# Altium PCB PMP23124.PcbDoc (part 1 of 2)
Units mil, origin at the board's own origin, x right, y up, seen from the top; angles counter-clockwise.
Board outline 2625 x 1500 mil, 2 copper layers (Top Layer, Bottom Layer), stack 62 mil thick; 59 components, 31 nets, 143 pads, 28 vias.
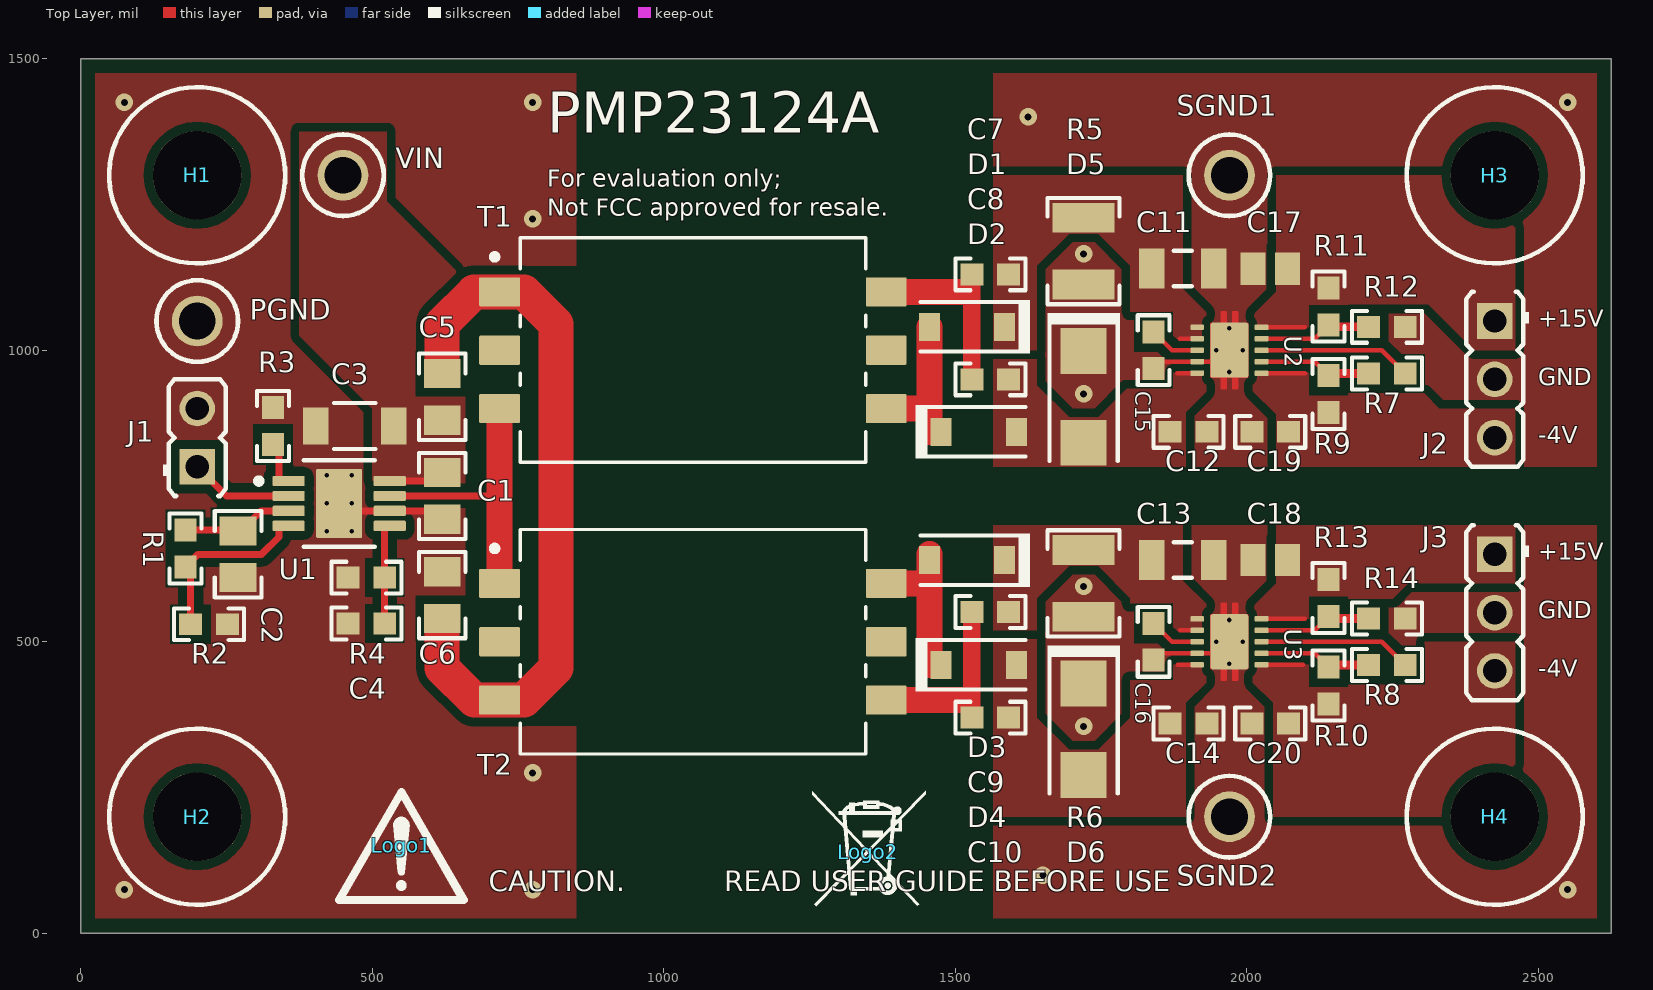
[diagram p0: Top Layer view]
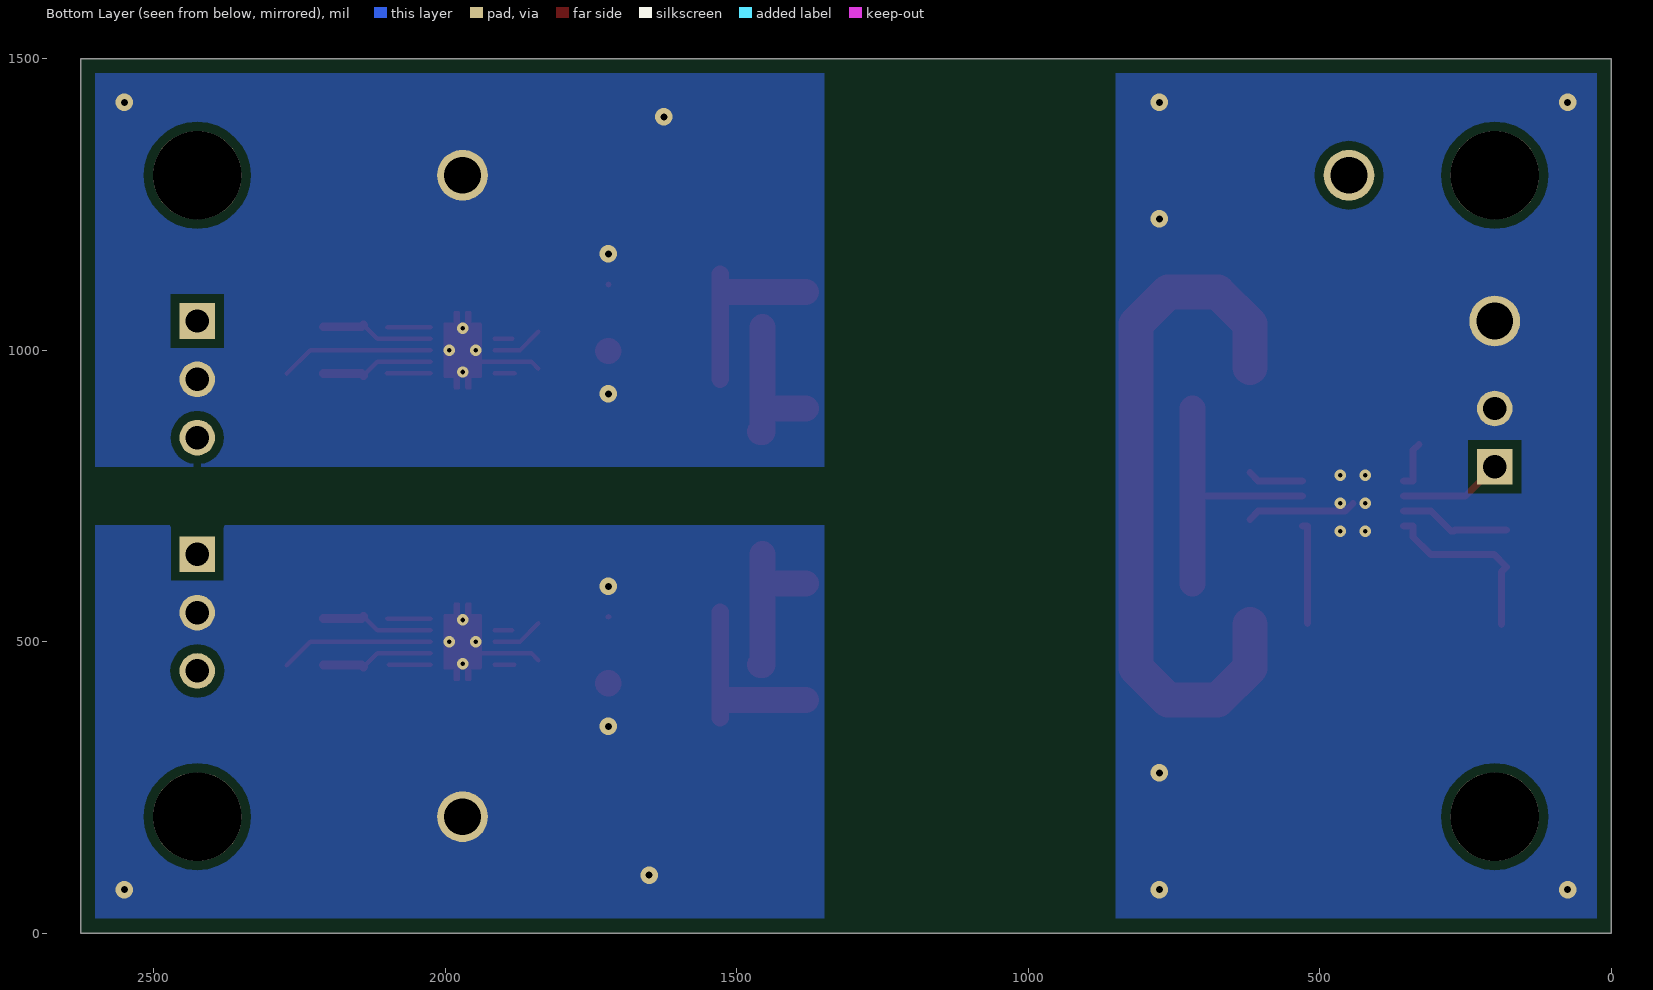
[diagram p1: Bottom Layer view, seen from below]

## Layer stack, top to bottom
Top Solder: solder mask 0.4, Solder Resist, Dk 3.5
Top Layer: signal copper 1.4
Dielectric1: core 59.2, FR-4 High Tg, Dk 4.8
Bottom Layer: signal copper 1.4
Bottom Solder: solder mask 0.4, Solder Resist, Dk 3.5

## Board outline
0,0 2625,0 2625,1500 0,1500

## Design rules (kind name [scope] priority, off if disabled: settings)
AcuteAngle [All] p1: minimum=4.50000000000000E+0001 checktracksonly=FALSE
AssemblyTestPointUsage [All] p1: valid=2
BoardOutlineClearance BoardOutlineClearance_MountingHoles [OnCopper and InComponentClass('Mounting Holes')] p1: gap=25 ignorepadtopadclearanceinfootprint=FALSE
BoardOutlineClearance BoardOutlineClearance_Poly [OnCopper and InPoly] p2: gap=25 ignorepadtopadclearanceinfootprint=FALSE
BoardOutlineClearance [OnCopper and Not InComponentClass('Logo') and not InComponentClass('FiducialMark') and not InRegion(1000,500,4000,800)] p3: gap=25 ignorepadtopadclearanceinfootprint=FALSE
Clearance Clearance_2 [InNetClass('HV') vs Not InNetClass('HV')] p1: gap=60 ignorepadtopadclearanceinfootprint=FALSE
Clearance Clearance_1 [InNetClass('MV') vs Not InNetClass('MV')] p2: gap=30 ignorepadtopadclearanceinfootprint=FALSE
Clearance Clearance_Keepouts [((IsTrack Or IsArc) And Not InPoly) And IsFree and IsKeepOut vs ((IsTrack Or IsArc) And Not InPoly) And IsFree and IsKeepOut] p3: gap=0 ignorepadtopadclearanceinfootprint=FALSE
Clearance Clearance_BoardEdge_MountingHoles [OnCopper and InComponentClass('Mounting Holes') vs IsKeepOut] p4: gap=40 ignorepadtopadclearanceinfootprint=FALSE except(0: Arc-Hole Track-Hole SMDPad-Hole THPad-Hole Via-Hole Fill-Hole Poly-Hole Region-Hole Text-Hole)
Clearance Clearance_BoardEdge_Poly [OnCopper and InPoly vs IsKeepOut] p5: gap=50 ignorepadtopadclearanceinfootprint=FALSE except(0: Arc-Hole Track-Hole SMDPad-Hole THPad-Hole Via-Hole Fill-Hole Poly-Hole Region-Hole Text-Hole)
Clearance Clearance_BoardEdge [OnCopper and Not InComponentClass('Logo') and not InComponentClass('FiducialMark') and not InRegion(1000,500,4000,800) and Not IsKeepout vs IsKeepOut] p6: gap=50 ignorepadtopadclearanceinfootprint=FALSE
Clearance Clearance_Poly [InPolygon] p7: gap=15 ignorepadtopadclearanceinfootprint=FALSE
Clearance [All] p8: gap=7.87 ignorepadtopadclearanceinfootprint=FALSE except(0: Arc-Hole Track-Hole SMDPad-Hole THPad-Hole Via-Hole Fill-Hole Poly-Hole Region-Hole Text-Hole)
ComponentClearance ComponentClearance_MountingHoles_FiducialMarks [InComponentClass('Mounting Holes') vs InComponentClass('FiducialMark')] p1: gap=20 collisioncheckmode=3 verticalgap=10 showdistances=FALSE
ComponentClearance ComponentClearance_Shunt [InComponentClass('Header') vs InComponentClass('Shunt')] p2: gap=0 collisioncheckmode=3 verticalgap=0 showdistances=FALSE
ComponentClearance ComponentClearance_Logo [InComponentClass('Logo')] p3: gap=5 collisioncheckmode=3 verticalgap=10 showdistances=FALSE
ComponentClearance ComponentClearance_ScrewToNut [(HasFootprint('NY PMS 440 0025 PH')) vs (HasFootprint('Keystone_1902C'))] p4: gap=20 collisioncheckmode=3 verticalgap=100000 showdistances=FALSE
ComponentClearance ComponentClearance_MountingHoles [InComponentClass('Mounting Holes')] p5: gap=20 collisioncheckmode=3 verticalgap=10 showdistances=FALSE
ComponentClearance ComponentClearance_SmallPassives [HasFootprint('0201*') or HasFootprint('0402*') or HasFootprint('0508') or HasFootprint('0603*') or HasFootprint('0612') or HasFootprint('0805*') or HasFootprint('0815*') or HasFootprint('0830*') or HasFootprint('1206*') or HasFootprint('1210*') or HasFootprint('1808*') or HasFootprint('1812*') or HasFootprint('1825*') or HasFootprint('2010*') or HasFootprint('2220*') or HasFootprint('2225*') or HasFootprint('2512*') or HasFootprint('2728*') or HasFootprint('3518*') vs HasFootprint('0201*') or HasFootprint('0402*') or HasFootprint('0508') or HasFootprint('0603*') or HasFootprint('0612') or HasFootprint('0805*') or HasFootprint('0815*') or HasFootprint('0830*') or HasFootprint('1206*') or HasFootprint('1210*') or HasFootprint('1808*') or HasFootprint('1812*') or HasFootprint('1825*') or HasFootprint('2010*') or HasFootprint('2220*') or HasFootprint('2225*') or HasFootprint('2512*') or HasFootprint('2728*') or HasFootprint('3518*')] p6: gap=20 collisioncheckmode=3 verticalgap=20 showdistances=FALSE
ComponentClearance ComponentClearance_THtoSMT [IsThruComponent vs IsSMTComponent] p7: gap=10 collisioncheckmode=3 verticalgap=10 showdistances=FALSE
ComponentClearance ComponentClearance_THtoTH [IsThruComponent vs IsThruComponent] p8: gap=10 collisioncheckmode=3 verticalgap=10 showdistances=FALSE
ComponentClearance [All] p9: gap=10 collisioncheckmode=3 verticalgap=10 showdistances=FALSE
DiffPairsRouting [All] p1: maxlimit=100 minlimit=10 mostfreqgap=10 toplayer_minwidth=15 toplayer_maxwidth=15 toplayer_prefwidth=15 bottomlayer_minwidth=15 bottomlayer_maxwidth=15 bottomlayer_prefwidth=15 maxuncoupledlength=1000
FabricationTestPointUsage TestPointUsage [All] p1: valid=2 allowmultiple=FALSE
FabricationTestpoint Testpoint [All] p1: side=3 testpointundercomponent=TRUE minsize=40 maxsize=100 preferedsize=60 minholesize=0 maxholesize=40 preferedholesize=32 testpointgrid=1 allowsidetop=TRUE allowsidebottom=TRUE usegrid=TRUE gridtolerance=0.01
FanoutControl Fanout_LCC [IsLCC] p1: bgadir=Out bgaviamode=Centered fanoutstyle=Auto fanoutdirection=Alternating viagrid=1 // Fanout_LCC (Default Rule)
FanoutControl Fanout_BGA [IsBGA] p2: bgadir=Out bgaviamode=Centered fanoutstyle=Auto fanoutdirection=Alternating viagrid=1 // Fanout_BGA (Default Rule)
FanoutControl Fanout_Default [All] p4: bgadir=Out bgaviamode=Centered fanoutstyle=Auto fanoutdirection=Alternating viagrid=1 // Fanout_Default (Default Rule)
FanoutControl Fanout_Small [(CompPinCount < 5)] p5: bgadir=Out bgaviamode=Centered fanoutstyle=Auto fanoutdirection=OutThenIn viagrid=1 // Fanout_Small (Default Rule)
Height [All] p1: minheight=0 maxheight=3000 prefheight=500
HoleSize [All] p1: absolutevalues=TRUE maxlimit=251 minlimit=7.87 maxpercent=80.000 minpercent=20.000
MinimumAnnularRing MinimumAnnularRing_ThermalPadVias [IsVia and InAnyComponent] p1: minimumring=5.91
MinimumAnnularRing [All] p2: minimumring=8
MinimumSolderMaskSliver MinimumSolderMaskSliver_Logo [InComponentClass('Logo') vs InComponentClass('Logo')] p1: minsoldermaskwidth=0.7
MinimumSolderMaskSliver [All] p2: minsoldermaskwidth=3.94
PlaneConnect [All] p1: planeconnectstyle=Direct reliefexpansion=10 reliefentries=4 reliefconductorwidth=10 reliefairgap=10
PolygonConnect PolygonConnect_15 [All vs IsNamedPolygon('C109_2') Or  IsNamedPolygon('C107_2') Or  IsNamedPolygon('HV') Or  IsNamedPolygon('Q203_5') Or  IsNamedPolygon('C107_2') Or  IsNamedPolygon('HS') Or  IsNamedPolygon('Q201_5') Or  IsNamedPolygon('Q203_5') Or  IsNamedPolygon('C106_2') Or  IsNamedPolygon('C108_2') Or  IsNamedPolygon('Vout') Or  IsNamedPolygon('Q203_5') Or  IsNamedPolygon('C108_2') Or  IsNamedPolygon('C113_2') Or  IsNamedPolygon('Q203_5') Or  IsNamedPolygon('Q201_5') Or  IsNamedPolygon('C107_2') Or  IsNamedPolygon('C102_1') Or  IsNamedPolygon('SGND') Or  IsNamedPolygon('GND') Or  IsNamedPolygon('SGND') Or  IsNamedPolygon('GND') Or  IsNamedPolygon('IN+') Or  IsNamedPolygon('IN+') Or  IsNamedPolygon('Q201_5') Or  IsNamedPolygon('Q201_5') Or  IsNamedPolygon('SGND') Or  IsNamedPolygon('SGND') Or  IsNamedPolygon('Vout') Or  IsNamedPolygon('Vout') Or  IsNamedPolygon('IN+') Or  IsNamedPolygon('GND') Or  IsNamedPolygon('IN+') Or  IsNamedPolygon('GND')] p1: connectstyle=Direct reliefconductorwidth=10 reliefentries=4 polygonreliefangle="90 Angle" airgapwidth=10
PolygonConnect PolygonConnect_14 [All vs IsNamedPolygon('C106_2') Or  IsNamedPolygon('C107_2') Or  IsNamedPolygon('C107_2') Or  IsNamedPolygon('C107_2') Or  IsNamedPolygon('C102_1') Or  IsNamedPolygon('Q203_5') Or  IsNamedPolygon('Vout') Or  IsNamedPolygon('Q203_5') Or  IsNamedPolygon('Q203_5') Or  IsNamedPolygon('Q201_5') Or  IsNamedPolygon('C108_2') Or  IsNamedPolygon('Q203_5') Or  IsNamedPolygon('HS') Or  IsNamedPolygon('HV') Or  IsNamedPolygon('C108_2') Or  IsNamedPolygon('Q201_5') Or  IsNamedPolygon('C109_2') Or  IsNamedPolygon('Q201_5') Or  IsNamedPolygon('Q201_5') Or  IsNamedPolygon('C113_2')] p2: connectstyle=Direct reliefconductorwidth=10 reliefentries=4 polygonreliefangle="90 Angle" airgapwidth=10
PolygonConnect PolygonConnect_13 [All vs IsNamedPolygon('C102_1') Or  IsNamedPolygon('HV') Or  IsNamedPolygon('C107_2') Or  IsNamedPolygon('C109_2') Or  IsNamedPolygon('C107_2') Or  IsNamedPolygon('C108_2') Or  IsNamedPolygon('C106_2') Or  IsNamedPolygon('C108_2') Or  IsNamedPolygon('C113_2') Or  IsNamedPolygon('C107_2')] p3: connectstyle=Direct reliefconductorwidth=10 reliefentries=4 polygonreliefangle="90 Angle" airgapwidth=10
PolygonConnect PolygonConnect_12 [All vs IsNamedPolygon('C107_2') Or  IsNamedPolygon('C113_2') Or  IsNamedPolygon('C106_2') Or  IsNamedPolygon('C107_2') Or  IsNamedPolygon('C107_2') Or  IsNamedPolygon('C102_1')] p4: connectstyle=Direct reliefconductorwidth=10 reliefentries=4 polygonreliefangle="90 Angle" airgapwidth=10
PolygonConnect PolygonConnect_11 [All vs IsNamedPolygon('C106_2') Or  IsNamedPolygon('C102_1') Or  IsNamedPolygon('C107_2') Or  IsNamedPolygon('C107_2') Or  IsNamedPolygon('C107_2')] p5: connectstyle=Direct reliefconductorwidth=10 reliefentries=4 polygonreliefangle="90 Angle" airgapwidth=10
PolygonConnect PolygonConnect_10 [All vs IsNamedPolygon('C106_2')] p6: connectstyle=Direct reliefconductorwidth=10 reliefentries=4 polygonreliefangle="90 Angle" airgapwidth=10
PolygonConnect PolygonConnect_9 [All vs IsNamedPolygon('C11_1') Or  IsNamedPolygon('Vin') Or  IsNamedPolygon('Vin') Or  IsNamedPolygon('5V') Or  IsNamedPolygon('D6_2') Or  IsNamedPolygon('Q3_3') Or  IsNamedPolygon('GND2') Or  IsNamedPolygon('GND2') Or  IsNamedPolygon('GND') Or  IsNamedPolygon('Q3_4') Or  IsNamedPolygon('12V5') Or  IsNamedPolygon('GND') Or  IsNamedPolygon('12V5') Or  IsNamedPolygon('D3_1')] p7: connectstyle=Direct reliefconductorwidth=10 reliefentries=4 polygonreliefangle="90 Angle" airgapwidth=10
PolygonConnect PolygonConnect_8 [All vs IsNamedPolygon('C11_1') Or  IsNamedPolygon('Vin') Or  IsNamedPolygon('12V5') Or  IsNamedPolygon('Q3_3') Or  IsNamedPolygon('GND2') Or  IsNamedPolygon('GND2') Or  IsNamedPolygon('5V') Or  IsNamedPolygon('Q3_4') Or  IsNamedPolygon('12V5')] p8: connectstyle=Direct reliefconductorwidth=10 reliefentries=4 polygonreliefangle="90 Angle" airgapwidth=10
PolygonConnect PolygonConnect_7 [All vs IsNamedPolygon('GND2') Or  IsNamedPolygon('GND2') Or  IsNamedPolygon('5V') Or  IsNamedPolygon('12V5') Or  IsNamedPolygon('12V5') Or  IsNamedPolygon('C11_1')] p9: connectstyle=Direct reliefconductorwidth=10 reliefentries=4 polygonreliefangle="90 Angle" airgapwidth=10
PolygonConnect PolygonConnect_6 [All vs IsNamedPolygon('GND2') Or  IsNamedPolygon('SGND') Or  IsNamedPolygon('GND1') Or  IsNamedPolygon('C901_1') Or  IsNamedPolygon('SGND') Or  IsNamedPolygon('GND2') Or  IsNamedPolygon('GND1')] p10: connectstyle=Direct reliefconductorwidth=10 reliefentries=4 polygonreliefangle="90 Angle" airgapwidth=10
PolygonConnect PolygonConnect_5 [All vs IsNamedPolygon('GND1') Or  IsNamedPolygon('GND1')] p11: connectstyle=Direct reliefconductorwidth=10 reliefentries=4 polygonreliefangle="90 Angle" airgapwidth=10
PolygonConnect PolygonConnect_4 [All vs IsNamedPolygon('C21_1') Or  IsNamedPolygon('C5_1') Or  IsNamedPolygon('C12_2') Or  IsNamedPolygon('C2_2') Or  IsNamedPolygon('C13_1') Or  IsNamedPolygon('C28_1') Or  IsNamedPolygon('C6_1') Or  IsNamedPolygon('GND') Or  IsNamedPolygon('GND2') Or  IsNamedPolygon('C14_1') Or  IsNamedPolygon('C13_1') Or  IsNamedPolygon('Q1_3') Or  IsNamedPolygon('C14_1') Or  IsNamedPolygon('C5_1') Or  IsNamedPolygon('GND2') Or  IsNamedPolygon('C28_1') Or  IsNamedPolygon('D5_2') Or  IsNamedPolygon('D6_2') Or  IsNamedPolygon('D2_1') Or  IsNamedPolygon('C12_2') Or  IsNamedPolygon('D2_1') Or  IsNamedPolygon('C4_1') Or  IsNamedPolygon('C4_1') Or  IsNamedPolygon('C2_2') Or  IsNamedPolygon('GND') Or  IsNamedPolygon('C33_1') Or  IsNamedPolygon('C9_1')] p12: connectstyle=Direct reliefconductorwidth=10 reliefentries=4 polygonreliefangle="90 Angle" airgapwidth=10
PolygonConnect PolygonConnect_3 [All vs IsNamedPolygon('C28_1') Or  IsNamedPolygon('C12_2') Or  IsNamedPolygon('C28_1') Or  IsNamedPolygon('C9_1') Or  IsNamedPolygon('D5_2') Or  IsNamedPolygon('C12_2') Or  IsNamedPolygon('C2_2') Or  IsNamedPolygon('C14_1') Or  IsNamedPolygon('C4_1') Or  IsNamedPolygon('C14_1') Or  IsNamedPolygon('D6_2') Or  IsNamedPolygon('GND2') Or  IsNamedPolygon('Q1_3') Or  IsNamedPolygon('C5_1') Or  IsNamedPolygon('D2_1') Or  IsNamedPolygon('C4_1') Or  IsNamedPolygon('C13_1') Or  IsNamedPolygon('C5_1') Or  IsNamedPolygon('C13_1') Or  IsNamedPolygon('C33_1') Or  IsNamedPolygon('D2_1') Or  IsNamedPolygon('GND') Or  IsNamedPolygon('GND') Or  IsNamedPolygon('GND2') Or  IsNamedPolygon('C2_2') Or  IsNamedPolygon('C6_1') Or  IsNamedPolygon('C21_1')] p13: connectstyle=Direct reliefconductorwidth=10 reliefentries=4 polygonreliefangle="90 Angle" airgapwidth=10
PolygonConnect PolygonConnect_2 [All vs IsNamedPolygon('C21_1') Or  IsNamedPolygon('C4_1') Or  IsNamedPolygon('D5_2') Or  IsNamedPolygon('C5_1') Or  IsNamedPolygon('C14_1') Or  IsNamedPolygon('C13_1') Or  IsNamedPolygon('C4_1') Or  IsNamedPolygon('C33_1') Or  IsNamedPolygon('C12_2') Or  IsNamedPolygon('D2_1') Or  IsNamedPolygon('C2_2') Or  IsNamedPolygon('C28_1') Or  IsNamedPolygon('C12_2') Or  IsNamedPolygon('D2_1') Or  IsNamedPolygon('C5_1') Or  IsNamedPolygon('Q1_3') Or  IsNamedPolygon('GND') Or  IsNamedPolygon('D6_2') Or  IsNamedPolygon('C6_1') Or  IsNamedPolygon('C2_2') Or  IsNamedPolygon('C14_1') Or  IsNamedPolygon('C28_1') Or  IsNamedPolygon('C13_1') Or  IsNamedPolygon('C9_1') Or  IsNamedPolygon('GND')] p14: connectstyle=Direct reliefconductorwidth=10 reliefentries=4 polygonreliefangle="90 Angle" airgapwidth=10
PolygonConnect PolygonConnect_1 [All vs IsNamedPolygon('C28_1') Or  IsNamedPolygon('D5_2') Or  IsNamedPolygon('C5_1') Or  IsNamedPolygon('C5_1') Or  IsNamedPolygon('D2_1') Or  IsNamedPolygon('C21_1') Or  IsNamedPolygon('C9_1') Or  IsNamedPolygon('C4_1') Or  IsNamedPolygon('C14_1') Or  IsNamedPolygon('C28_1') Or  IsNamedPolygon('C6_1') Or  IsNamedPolygon('C12_2') Or  IsNamedPolygon('C33_1') Or  IsNamedPolygon('C4_1') Or  IsNamedPolygon('C13_1') Or  IsNamedPolygon('C12_2') Or  IsNamedPolygon('D6_2') Or  IsNamedPolygon('C2_2') Or  IsNamedPolygon('C14_1') Or  IsNamedPolygon('D2_1') Or  IsNamedPolygon('C2_2') Or  IsNamedPolygon('C13_1')] p15: connectstyle=Direct reliefconductorwidth=10 reliefentries=4 polygonreliefangle="90 Angle" airgapwidth=10
PolygonConnect [All] p16: connectstyle=Direct reliefconductorwidth=10 reliefentries=4 polygonreliefangle="90 Angle" airgapwidth=10
RoutingVias ThermalPadVias [IsVia and InAnyComponent] p1: holewidth=7.87 width=19.68 viastyle="Through Hole" minholewidth=7.87 minwidth=19.68 maxholewidth=12.99 maxwidth=23.62
RoutingVias [All] p2: holewidth=16 width=34 viastyle="Through Hole" minholewidth=7.87 minwidth=20 maxholewidth=40 maxwidth=65
SilkToBoardRegionClearance [Not ((IsComment or IsDesignator) And (Hide <> 'False')) and not InRegion(1000,500,4000,800)] p1:
SilkToSilkClearance SilkToSilkClearance_Pb-FreeLogo [(HasFootprint('Pb-Free_Overlay_Medium') OR HasFootprint('Pb-Free_Overlay_Small')) vs (HasFootprint('Pb-Free_Overlay_Medium') OR HasFootprint('Pb-Free_Overlay_Small'))] p1: silktosilkclearance=0
SilkToSilkClearance [All] p2: silktosilkclearance=4
SilkToSolderMaskClearance SilkToComponentPadClearance [IsPad and InAnycomponent] p1: minsilkscreentomaskgap=5 clearancetoexposedcopper=TRUE
SilkToSolderMaskClearance "Silk to Solder Mask Opening" [All] p2: minsilkscreentomaskgap=4 clearancetoexposedcopper=FALSE
SolderMaskExpansion [All] p1: expansion=1.97 istentingtop=FALSE
Width [All] p1: maxlimit=100 minlimit=6 preferedwidth=10 checkconnectedcopper=TRUE
14 further rules are at their usual default settings.

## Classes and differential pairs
component class Header: J1 J2 J3

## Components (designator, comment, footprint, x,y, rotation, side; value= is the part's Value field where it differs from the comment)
C1 "GRM219R7YA105KA12D" 0805_HV 620,750 r270 top value=1uF
C2 "GRM219R7YA105KA12D" 0805_HV 270,650 r270 top value=1uF
C3 "GRM31CR71H475KA12L" 1206_180 470,870 r180 top value=4.7uF
C4 "GRM1885C1H101JA01D" 0603 490,531.49 r180 top value=100pF
C5 "GRM219R7YA105KA12D" 0805_HV 620,920 r90 top value=1uF
C6 "GRM219R7YA105KA12D" 0805_HV 620,580 r90 top value=1uF
C7 "GRM188R71H223KA01D" 0603 1560,1130 r0 top value=0.022uF
C8 "GRM188R71H223KA01D" 0603 1560,950 r180 top value=0.022uF
C9 "GRM188R71H223KA01D" 0603 1560,550.89 r0 top value=0.022uF
C10 "GRM188R71H223KA01D" 0603 1560,370 r180 top value=0.022uF
C11 "GRM31CR71H475KA12L" 1206_180L 1890,1140 r0 top value=4.7uF
C12 "GRM188Z71C475KE21D" 0603 1900,860 r180 top value=4.7uF
C13 "GRM31CR71H475KA12L" 1206_180L 1890,640 r0 top value=4.7uF
C14 "GRM188Z71C475KE21D" 0603 1900,360 r180 top value=4.7uF
C15 "GRM188R71C103KA01D" 0603 1840,1000 r270 top value=0.01uF
C16 "GRM188R71C103KA01D" 0603 1840,500 r270 top value=0.01uF
C17 "GRM21BZ71E106KE15L" 0805L 2040,1139.76 r180 top value=10uF
C18 "GRM21BZ71E106KE15L" 0805L 2040,640 r180 top value=10uF
C19 "GRM188Z71A106MA73D" 0603 2040,860 r180 top value=10uF
C20 "GRM188Z71A106MA73D" 0603 2040,360 r180 top value=10uF
D1 "PMEG6010CEGWJ" SOD-123 1520,1040 r180 top value=60V
D2 "PMEG6010CEGWJ" SOD-123 1540,860 r0 top value=60V
D3 "PMEG6010CEGWJ" SOD-123 1520,640 r180 top value=60V
D4 "PMEG6010CEGWJ" SOD-123 1540,460.42 r0 top value=60V
D5 "SMAZ5V1-13-F" SMA 1720,920 r270 top value=5.1V
D6 "SMAZ5V1-13-F" SMA 1720,350 r270 top value=5.1V
H1 "4824" KEYSTONE_4824 200,1300 r0 top
H2 "4824" KEYSTONE_4824 200,200 r0 top
H3 "4824" KEYSTONE_4824 2425,1300 r0 top
H4 "4824" KEYSTONE_4824 2425,200 r0 top
J1 "22284023" Molex_0022284023 200,850 r90 top
J2 "22284033" Molex_0022284033 2425,950 r270 top
J3 "22284033" Molex_0022284033 2425,550 r270 top
Logo1 "CAUTION.           READ USER GUIDE BEFORE USE" IEC_Caution_Small 550,150 r0 top
Logo2 "WEEE logo" WEEE_Minimum 1350,140 r0 top
Logo3 "FCC disclaimer" FCC_disclaimer 1300,1710 r0 top
PGND "5011" Keystone5011 200,1050 r90 top
R1 "CRCW06033K24FKEA" 0603 180,660 r90 top value=3.24k
R2 "CRCW060311K0FKEA" 0603 220,530 r180 top value=11.0k
R3 "CRCW060310K0FKEA" 0603 330,870 r270 top value=10.0k
R4 "CRCW060360K4FKEA" 0603 490,610 r0 top value=60.4k
R5 "RC1210JR-074K7L" 1210 1720,1170 r90 top value=4.7k
R6 "RC1210JR-074K7L" 1210 1720,600 r90 top value=4.7k
R7 "CRCW060310K0FKEA" 0603 2240,960 r0 top value=10.0k
R8 "CRCW060310K0FKEA" 0603 2240,460 r0 top value=10.0k
R9 "CRCW060334K0FKEA" 0603 2140,925 r90 top value=34.0k
R10 "CRCW060334K0FKEA" 0603 2140,425 r90 top value=34.0k
R11 "CRCW0603115KFKEA" 0603 2140,1075 r90 top value=115k
R12 "CRCW060310K0FKEA" 0603 2240,1040 r0 top value=10.0k
R13 "CRCW0603115KFKEA" 0603 2140,575 r90 top value=115k
R14 "CRCW060310K0FKEA" 0603 2240,540 r0 top value=10.0k
SGND1 "5011" Keystone5011 1970,1300 r90 top
SGND2 "5011" Keystone5011 1970,200 r90 top
T1 "RLTI-1404" FP-RLTI-1404_TRANSFORMER_0IN577_0IN37-MFG 1050,1000 r0 top
T2 "RLTI-1404" FP-RLTI-1404_TRANSFORMER_0IN577_0IN37-MFG 1050,500 r0 top
U1 "UCC25800DGNRQ1" DGN0008G-MFG 443.39,737.2 r0 top
U2 "TPS7A3901DSCR" DSC0010J 1970,1000 r0 top
U3 "TPS7A3901DSCR" DSC0010J 1970,500 r0 top
VIN "5010" Keystone5010 450,1300 r0 top

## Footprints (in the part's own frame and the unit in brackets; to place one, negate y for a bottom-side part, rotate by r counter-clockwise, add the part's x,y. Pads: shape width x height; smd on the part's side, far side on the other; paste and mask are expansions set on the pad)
0603 [mm] "0603 from SM-752 data"
  rect 1x0.95 smd: 1(-0.8,0) 2(0.8,0)
  silkscreen extent -1.52,-0.69 1.52,0.69, body extent -0.87,-0.47 0.87,0.47, height 1
0805_HV [mil] "0805 with 30mil clearance between pads"
  rect 50x63 smd: 1(-40,0) 2(40,0)
  silkscreen extent -74,-40 74,40, body extent -43,-29 43,29, height 57
0805L [mm] "0805 from SM-752 data"
  rect 1.1x1.4 smd: 1(-0.75,0) 2(0.75,0)
  body extent -1.1,-0.72 1.1,0.72, height 1.45
1206_180 [mm] "1206_180"
  rect 1.1x1.6 smd: 1(-1.7,0) 2(1.7,0)
  silkscreen extent -0.9,-1 0.9,1, body extent -1.75,-0.95 1.75,0.95, height 1.8
1206_180L [mm] "1206_180"
  rect 1.1x1.75 smd: 1(-1.35,0) 2(1.35,0)
  silkscreen extent -0.4,-0.77 0.4,0.77, body extent -1.75,-0.95 1.75,0.95, height 1.8
1210 [mm] "1210 from SM-752 data"
  rect 1.3x2.7 smd: 1(-1.45,0) 2(1.45,0)
  silkscreen extent -2.32,-1.57 2.32,1.57, body extent -1.7,-1.35 1.7,1.35, height 1.35
DGN0008G-MFG [mm]
  rrect22% 1.4x0.45 smd paste+0 mask+0: 1(-2.2,0.975) 2(-2.2,0.325) 3(-2.2,-0.325) 4(-2.2,-0.975) 5(2.2,-0.975) 6(2.2,-0.325) 7(2.2,0.325) 8(2.2,0.975)
  rrect5% 2x3 smd paste-1000 mask-1000: 9(0,0)
  silkscreen extent -3.62,-1.88 1.55,1.88, body extent -3,-1.8 3,1.8, height 0.25
DSC0010J [mm] "WSON-10"
  rrect42% 0.6x0.24 smd: 1(-1.4,1) 2(-1.4,0.5) 3(-1.4,0) 4(-1.4,-0.5) 5(-1.4,-1) 6(1.4,-1) 7(1.4,-0.5) 8(1.4,0) 9(1.4,0.5) 10(1.4,1)
  rrect12% 1.65x2.4 smd paste-1 mask-2: 11(0,0)
  Top Layer region: -0.375,-1.65 -0.375,-1.2 -0.775,-1.2 -0.794,-1.196 -0.81,-1.185 -0.821,-1.169 -0.825,-1.15 -0.825,-1.15 -0.825,1.15 -0.821,1.169 -0.81,1.185 -0.794,1.196 -0.775,1.2 -0.775,1.2 -0.375,1.2 -0.375,1.65 -0.371,1.669 -0.36,1.685 -0.344,1.696 -0.325,1.7 -0.325,1.7 -0.325,1.7 -0.175,1.7 -0.175,1.7 -0.156,1.696 -0.14,1.685 -0.129,1.669 -0.125,1.65 -0.125,1.65 -0.125,1.2 0.125,1.2 0.125,1.65 0.129,1.669 0.14,1.685 0.156,1.696 0.175,1.7 0.175,1.7 0.175,1.7 0.325,1.7 0.325,1.7 0.344,1.696 0.36,1.685 0.371,1.669 0.375,1.65 0.375,1.65 0.375,1.2 0.775,1.2 0.794,1.196 0.81,1.185 0.821,1.169 0.825,1.15 0.825,1.15 0.825,-1.15 0.821,-1.169 0.81,-1.185 0.794,-1.196 0.775,-1.2 0.775,-1.2 0.375,-1.2 0.375,-1.65 0.371,-1.669 0.36,-1.685 0.344,-1.696 0.325,-1.7 0.325,-1.7 0.175,-1.7 0.156,-1.696 0.14,-1.685 0.129,-1.669 0.125,-1.65 0.125,-1.65 0.125,-1.2 -0.125,-1.2 -0.125,-1.65 -0.129,-1.669 -0.14,-1.685 -0.156,-1.696 -0.175,-1.7 -0.175,-1.7 -0.325,-1.7 -0.344,-1.696 -0.36,-1.685 -0.371,-1.669 -0.375,-1.65
  body extent -1.5,-1.5 1.5,1.5, height 0.8
FCC_disclaimer [mil]
FP-RLTI-1404_TRANSFORMER_0IN577_0IN37-MFG [mil]
  rrect8% 70x50 smd paste+0 mask+0: 1(-331.5,100) 2(-331.5,0) 3(-331.5,-100) 4(331.5,-100) 5(331.5,0) 6(331.5,100)
  silkscreen extent -345,-192 296,192, body extent -370,-196 370,196, height 10
IEC_Caution_Small [mil]
  silkscreen extent -107,-93 107,92
Keystone5010 [mil] "Keystone Multipurpose loops"
  round 87 hole 63: 1(0,0)
  silkscreen extent -70,-70 70,70, body extent -63,-63 63,62, height 319
Keystone5011 [mil] "Keystone Multipurpose loops"
  round 87 hole 63: 1(0,0)
  silkscreen extent -70,-70 70,70, body extent -63,-63 63,62, height 319
KEYSTONE_4824 [mil] "HEX STANDOFF 6-32 NYLON 1-1/2\""
  round 1 on Mech3: 0(0,0)
  round 152 hole 152 unplated: MH(0,0)
  silkscreen extent -151,-151 151,151, body extent -144,-125 144,125, height 1500
Molex_0022284023 [mm] "Header, 2.54mm, 2x1, TH"
  rect 1.55x1.55 hole 1.02: 1(-1.27,0)
  round 1.55 hole 1.02: 2(1.27,0)
  silkscreen extent -2.54,-1.24 2.54,1.5, body extent -2.54,-1.24 2.54,1.24, height 8.4
Molex_0022284033 [mm] "Header, 2.54mm, 3x1, TH"
  rect 1.55x1.55 hole 1.02: 1(-2.54,0)
  round 1.55 hole 1.02: 2(0,0) 3(2.54,0)
  silkscreen extent -3.81,-1.24 3.81,1.5, body extent -3.81,-1.24 3.81,1.24, height 8.4
SMA [mm] "Molded Diode, 2-Leads, Body 4.3x2.6mm, IPC Medium Density, based on OnSemi component dimensions and land pattern"
  rect 2x2 smd: 1(-2,0) 2(2,0)
  silkscreen extent -3.66,-1.57 2.79,1.57, body extent -2.6,-1.3 2.6,1.3, height 2.42
SOD-123 [mm] "On Semi recommended land pattern"
  rect 0.915x1.22 smd: 1(-1.637,0) 2(1.637,0)
  silkscreen extent -2.74,-1.17 2.03,1.17, body extent -1.93,-0.9 1.93,0.9, height 1.35
WEEE_Minimum [mil] "WEEElie bin"
  silkscreen extent -95,-94 99,104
